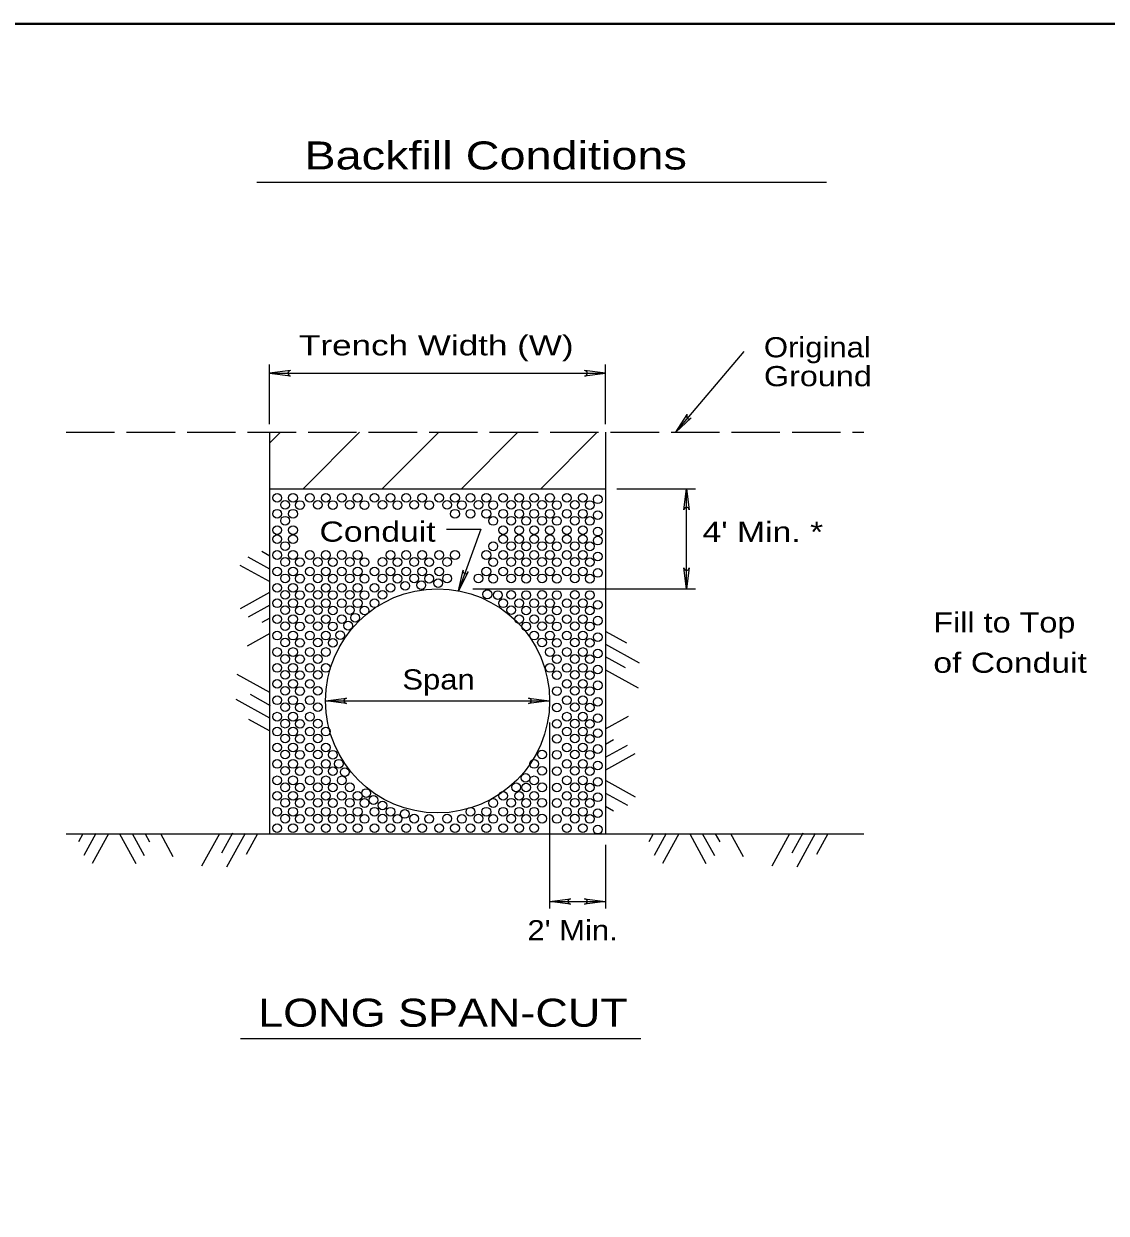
# Model space of a CAD drawing. Extents: x 750.7 to 784.7, y 834.8 to 878.8.
# Drawn here: x 763.05 to 772.71, y 845.67 to 856.28 of the extents above; entities that cross this region are included whole.
import ezdxf

# ---------------------------------------------------------------- set-up
doc = ezdxf.new("R2010")
doc.units = 0
doc.header["$LTSCALE"] = 0.072
doc.linetypes.add('LONG_DASHED', pattern=[7.5, 6, -1.5])
doc.layers.add('1', color=7, linetype='Continuous', lineweight=13)
doc.layers.add('47', color=7, linetype='Continuous', lineweight=13)

msp = doc.modelspace()

# ---------------------------------------------------------------- linework, layer by layer
at = {"layer": '1', "lineweight": 40}
msp.add_line((752.65083, 856.28433), (784.15083, 856.28433), dxfattribs=at)
at = {"layer": '1'}
for p, q in [((765.12592, 854.87), (770.20992, 854.87)), ((768.86525, 852.63842), (769.47633, 853.36033)), ((765.2395, 852.71117), (765.2395, 853.24292)), ((768.2395, 852.71117), (768.2395, 853.24292)), ((765.2395, 853.16492), (768.2395, 853.16492)), ((765.2395, 852.63842), (765.2395, 849.05517)), ((765.2395, 852.54192), (765.336, 852.63842)), ((765.53858, 852.13383), (766.04308, 852.63842)), ((766.24567, 852.13383), (766.75017, 852.63842)), ((766.95275, 852.13383), (767.45725, 852.63842)), ((767.65983, 852.13383), (768.16433, 852.63842)), ((768.2395, 852.63842), (768.2395, 849.05517)), ((765.2395, 852.13383), (768.2395, 852.13383)), ((768.3405, 852.13383), (769.04183, 852.13383)), ((768.96192, 851.24025), (768.96192, 852.13383)), ((765.24342, 851.41692), (765.04792, 851.52475)), ((765.242, 851.5335), (765.17067, 851.57283)), ((765.2395, 851.30483), (764.97692, 851.44975)), ((765.2395, 851.20692), (764.97692, 851.062)), ((767.05342, 851.24025), (769.04183, 851.24025)), ((765.24342, 851.09483), (765.04792, 850.987)), ((765.242, 850.97825), (765.17067, 850.93892)), ((765.2425, 850.84192), (765.03842, 850.72933)), ((768.242, 850.85983), (768.42642, 850.75808)), ((768.23808, 850.74775), (768.53925, 850.58158)), ((768.23417, 850.63575), (768.41258, 850.53733)), ((765.242, 850.31475), (764.951, 850.47533)), ((768.2395, 850.51858), (768.5305, 850.358)), ((765.24342, 850.08558), (764.94225, 850.25175)), ((765.24733, 850.19758), (765.06892, 850.296)), ((765.7395, 850.2405), (767.7395, 850.2405)), ((768.239, 849.99142), (768.44308, 850.104)), ((765.2395, 849.9735), (765.05508, 850.07525)), ((767.7395, 850.04683), (767.7395, 848.38733)), ((768.2395, 849.85508), (768.31083, 849.89442)), ((768.23808, 849.7385), (768.43358, 849.84633)), ((768.242, 849.62642), (768.50458, 849.77133)), ((768.242, 849.5285), (768.50458, 849.38358)), ((768.23808, 849.41642), (768.43358, 849.30858)), ((768.2395, 849.29983), (768.31083, 849.2605)), ((763.42408, 849.05517), (770.54342, 849.05517)), ((763.57342, 849.05517), (763.53408, 848.98383)), ((763.69, 849.05658), (763.58217, 848.86108)), ((763.80208, 849.05267), (763.65717, 848.79008)), ((763.9, 849.05267), (764.04492, 848.79008)), ((764.01208, 849.05658), (764.11992, 848.86108)), ((764.12867, 849.05517), (764.168, 848.98383)), ((764.265, 849.05567), (764.37758, 848.85158)), ((764.79217, 849.05517), (764.63158, 848.76417)), ((764.90933, 849.0605), (764.81092, 848.88208)), ((765.02133, 849.05658), (764.85517, 848.75542)), ((765.13342, 849.05267), (765.03167, 848.86825)), ((768.66358, 849.05517), (768.62425, 848.98383)), ((768.78017, 849.05658), (768.67233, 848.86108)), ((768.89225, 849.05267), (768.74733, 848.79008)), ((768.99017, 849.05267), (769.13508, 848.79008)), ((769.10225, 849.05658), (769.21008, 848.86108)), ((769.21883, 849.05517), (769.25817, 848.98383)), ((769.35517, 849.05567), (769.46775, 848.85158)), ((769.88233, 849.05517), (769.72175, 848.76417)), ((769.9995, 849.0605), (769.90108, 848.88208)), ((770.1115, 849.05658), (769.94533, 848.75542)), ((770.22358, 849.05267), (770.12183, 848.86825)), ((768.2395, 848.95567), (768.2395, 848.38733)), ((767.7395, 848.4495), (768.2395, 848.4495)), ((764.97883, 847.22583), (768.55458, 847.22583))]:
    msp.add_line(p, q, dxfattribs=at)
at = {"layer": '1', "linetype": 'LONG_DASHED'}
msp.add_line((763.42408, 852.63842), (770.54342, 852.63842), dxfattribs=at)
at = {"layer": '1', "lineweight": 40}
msp.add_lwpolyline([(784.15083, 835.28433), (752.65083, 835.28433), (752.65083, 856.28433), (784.15083, 856.28433)], dxfattribs=at)
at = {"layer": '1'}
msp.add_lwpolyline([(766.82042, 851.77392), (767.12475, 851.77392), (766.92558, 851.223)], dxfattribs=at)
for centre, radius in [((765.30705, 852.05311), 0.03892), ((765.37808, 851.99097), 0.03892), ((765.44908, 852.05314), 0.03892), ((765.51124, 851.98864), 0.03892), ((765.59996, 852.05311), 0.03892), ((765.67099, 851.99097), 0.03892), ((765.74199, 852.05314), 0.03892), ((765.80416, 851.98864), 0.03892), ((765.88405, 852.05311), 0.03892), ((765.95508, 851.99097), 0.03892), ((766.02608, 852.05314), 0.03892), ((766.08824, 851.98864), 0.03892), ((766.17696, 852.05311), 0.03892), ((766.24799, 851.99097), 0.03892), ((766.31899, 852.05314), 0.03892), ((766.38116, 851.98864), 0.03892), ((766.46005, 852.05311), 0.03892), ((766.53108, 851.99097), 0.03892), ((766.60208, 852.05314), 0.03892), ((766.66424, 851.98864), 0.03892), ((766.75296, 852.05311), 0.03892), ((766.82399, 851.99097), 0.03892), ((766.89499, 852.05314), 0.03892), ((766.95716, 851.98864), 0.03892), ((767.03263, 852.05311), 0.03892), ((767.10366, 851.99097), 0.03892), ((767.17466, 852.05314), 0.03892), ((767.23683, 851.98864), 0.03892), ((767.32555, 852.05311), 0.03892), ((767.39658, 851.99097), 0.03892), ((767.46758, 852.05314), 0.03892), ((767.52974, 851.98864), 0.03892), ((767.6008, 852.05311), 0.03892), ((767.67183, 851.99097), 0.03892), ((767.74283, 852.05314), 0.03892), ((767.80499, 851.98864), 0.03892), ((767.89371, 852.05311), 0.03892), ((767.96474, 851.99097), 0.03892), ((768.03574, 852.05314), 0.03892), ((768.09791, 851.98864), 0.03892), ((768.16891, 852.03981), 0.03892), ((765.30705, 851.91103), 0.03892), ((765.44908, 851.91106), 0.03892), ((766.89499, 851.91106), 0.03892), ((767.03263, 851.91103), 0.03892), ((767.17466, 851.91106), 0.03892), ((767.32555, 851.91103), 0.03892), ((767.46758, 851.91106), 0.03892), ((767.6008, 851.91103), 0.03892), ((767.74283, 851.91106), 0.03892), ((767.89371, 851.91103), 0.03892), ((768.03574, 851.91106), 0.03892), ((768.16891, 851.89772), 0.03892), ((765.30705, 851.76453), 0.03892), ((765.37808, 851.84889), 0.03892), ((765.44908, 851.76456), 0.03892), ((767.23683, 851.84656), 0.03892), ((767.32555, 851.76453), 0.03892), ((767.39658, 851.84889), 0.03892), ((767.46758, 851.76456), 0.03892), ((767.52974, 851.84656), 0.03892), ((767.6008, 851.76453), 0.03892), ((767.67183, 851.84889), 0.03892), ((767.74283, 851.76456), 0.03892), ((767.80499, 851.84656), 0.03892), ((767.89371, 851.76453), 0.03892), ((767.96474, 851.84889), 0.03892), ((768.03574, 851.76456), 0.03892), ((768.09791, 851.84656), 0.03892), ((765.30705, 851.68461), 0.03892), ((765.44908, 851.68464), 0.03892), ((767.32555, 851.68461), 0.03892), ((767.46758, 851.68464), 0.03892), ((767.6008, 851.68461), 0.03892), ((767.74283, 851.68464), 0.03892), ((767.89371, 851.68461), 0.03892), ((768.03574, 851.68464), 0.03892), ((768.16891, 851.75122), 0.03892), ((768.16891, 851.67131), 0.03892), ((765.37808, 851.62247), 0.03892), ((767.23683, 851.62014), 0.03892), ((767.39658, 851.62247), 0.03892), ((767.52974, 851.62014), 0.03892), ((767.67183, 851.62247), 0.03892), ((767.80499, 851.62014), 0.03892), ((767.96474, 851.62247), 0.03892), ((768.09791, 851.62014), 0.03892), ((765.30705, 851.54253), 0.03892), ((765.37808, 851.48039), 0.03892), ((765.44908, 851.54256), 0.03892), ((765.51124, 851.47806), 0.03892), ((765.59996, 851.54253), 0.03892), ((765.67099, 851.48039), 0.03892), ((765.74199, 851.54256), 0.03892), ((765.80416, 851.47806), 0.03892), ((765.88405, 851.54253), 0.03892), ((765.95508, 851.48039), 0.03892), ((766.02608, 851.54256), 0.03892), ((766.08824, 851.47806), 0.03892), ((766.24799, 851.48039), 0.03892), ((766.31899, 851.54256), 0.03892), ((766.38116, 851.47806), 0.03892), ((766.46005, 851.54253), 0.03892), ((766.53108, 851.48039), 0.03892), ((766.60208, 851.54256), 0.03892), ((766.66424, 851.47806), 0.03892), ((766.75296, 851.54253), 0.03892), ((766.82399, 851.48039), 0.03892), ((766.89499, 851.54256), 0.03892), ((767.17466, 851.54256), 0.03892), ((767.23683, 851.47806), 0.03892), ((767.32555, 851.54253), 0.03892), ((767.39658, 851.48039), 0.03892), ((767.46758, 851.54256), 0.03892), ((767.52974, 851.47806), 0.03892), ((767.6008, 851.54253), 0.03892), ((767.67183, 851.48039), 0.03892), ((767.74283, 851.54256), 0.03892), ((767.80499, 851.47806), 0.03892), ((767.89371, 851.54253), 0.03892), ((767.96474, 851.48039), 0.03892), ((768.03574, 851.54256), 0.03892), ((768.09791, 851.47806), 0.03892), ((768.16891, 851.52922), 0.03892), ((765.30705, 851.39603), 0.03892), ((765.37808, 851.33389), 0.03892), ((765.44908, 851.39606), 0.03892), ((765.59996, 851.39603), 0.03892), ((765.67099, 851.33389), 0.03892), ((765.74199, 851.39606), 0.03892), ((765.88405, 851.39603), 0.03892), ((765.95508, 851.33389), 0.03892), ((766.02608, 851.39606), 0.03892), ((766.17696, 851.39603), 0.03892), ((766.24799, 851.33389), 0.03892), ((766.31899, 851.39606), 0.03892), ((766.46005, 851.39603), 0.03892), ((766.53108, 851.33389), 0.03892), ((766.60208, 851.39606), 0.03892), ((766.75296, 851.39603), 0.03892), ((766.82399, 851.33389), 0.03892), ((767.10366, 851.33389), 0.03892), ((767.17466, 851.39606), 0.03892), ((767.32555, 851.39603), 0.03892), ((767.39658, 851.33389), 0.03892), ((767.46758, 851.39606), 0.03892), ((767.6008, 851.39603), 0.03892), ((767.67183, 851.33389), 0.03892), ((767.74283, 851.39606), 0.03892), ((767.89371, 851.39603), 0.03892), ((767.96474, 851.33389), 0.03892), ((768.03574, 851.39606), 0.03892), ((768.16891, 851.38272), 0.03892), ((765.30705, 851.24944), 0.03892), ((765.44908, 851.24947), 0.03892), ((765.51124, 851.33156), 0.03892), ((765.59996, 851.24944), 0.03892), ((765.74199, 851.24947), 0.03892), ((765.80416, 851.33156), 0.03892), ((765.88405, 851.24944), 0.03892), ((766.02608, 851.24947), 0.03892), ((766.08824, 851.33156), 0.03892), ((766.17696, 851.24944), 0.03892), ((766.31899, 851.24947), 0.03892), ((766.38116, 851.33156), 0.03892), ((766.45115, 851.26725), 0.03892), ((766.59425, 851.27379), 0.03892), ((766.66424, 851.33156), 0.03892), ((766.74508, 851.29154), 0.03892), ((767.23683, 851.33156), 0.03892), ((767.52974, 851.33156), 0.03892), ((767.80499, 851.33156), 0.03892), ((768.09791, 851.33156), 0.03892), ((765.37808, 851.18731), 0.03892), ((765.51124, 851.18497), 0.03892), ((765.67099, 851.18731), 0.03892), ((766.7395, 850.2405), 1), ((765.80416, 851.18497), 0.03892), ((765.95508, 851.18731), 0.03892), ((766.08824, 851.18497), 0.03892), ((766.24799, 851.18731), 0.03892), ((767.18356, 851.1917), 0.03892), ((767.27675, 851.18495), 0.03892), ((767.39658, 851.18731), 0.03892), ((767.52974, 851.18497), 0.03892), ((767.67183, 851.18731), 0.03892), ((767.80499, 851.18497), 0.03892), ((767.96474, 851.18731), 0.03892), ((768.09791, 851.18497), 0.03892), ((765.30705, 851.11178), 0.03892), ((765.37808, 851.04964), 0.03892), ((765.44908, 851.11181), 0.03892), ((765.51124, 851.04731), 0.03892), ((765.59996, 851.11178), 0.03892), ((765.67099, 851.04964), 0.03892), ((765.74199, 851.11181), 0.03892), ((765.80416, 851.04731), 0.03892), ((765.88405, 851.11178), 0.03892), ((765.95508, 851.04964), 0.03892), ((766.02608, 851.11181), 0.03892), ((766.08824, 851.04731), 0.03892), ((766.17696, 851.11178), 0.03892), ((767.32555, 851.11178), 0.03892), ((767.39658, 851.04964), 0.03892), ((767.46758, 851.11181), 0.03892), ((767.52974, 851.04731), 0.03892), ((767.6008, 851.11178), 0.03892), ((767.67183, 851.04964), 0.03892), ((767.74283, 851.11181), 0.03892), ((767.80499, 851.04731), 0.03892), ((767.89371, 851.11178), 0.03892), ((767.96474, 851.04964), 0.03892), ((768.03574, 851.11181), 0.03892), ((768.09791, 851.04731), 0.03892), ((768.16891, 851.09847), 0.03892), ((765.30705, 850.96969), 0.03892), ((765.44908, 850.96972), 0.03892), ((765.59996, 850.96969), 0.03892), ((765.74199, 850.96972), 0.03892), ((765.88405, 850.96969), 0.03892), ((765.94175, 850.91202), 0.03892), ((766.00384, 850.98305), 0.03892), ((767.46758, 850.96972), 0.03892), ((767.6008, 850.96969), 0.03892), ((767.74283, 850.96972), 0.03892), ((767.89371, 850.96969), 0.03892), ((768.03574, 850.96972), 0.03892), ((768.16891, 850.95639), 0.03892), ((765.30705, 850.82319), 0.03892), ((765.37808, 850.90756), 0.03892), ((765.44908, 850.82322), 0.03892), ((765.51124, 850.90522), 0.03892), ((765.59996, 850.82319), 0.03892), ((765.67099, 850.90756), 0.03892), ((765.74199, 850.82322), 0.03892), ((765.80416, 850.90522), 0.03892), ((765.87075, 850.82761), 0.03892), ((767.52974, 850.90522), 0.03892), ((767.6008, 850.82319), 0.03892), ((767.67183, 850.90756), 0.03892), ((767.74283, 850.82322), 0.03892), ((767.80499, 850.90522), 0.03892), ((767.89371, 850.82319), 0.03892), ((767.96474, 850.90756), 0.03892), ((768.03574, 850.82322), 0.03892), ((768.09791, 850.90522), 0.03892), ((768.16891, 850.80989), 0.03892), ((765.37808, 850.76106), 0.03892), ((765.51124, 850.75872), 0.03892), ((765.67099, 850.76106), 0.03892), ((765.80416, 850.75872), 0.03892), ((767.67183, 850.76106), 0.03892), ((767.80499, 850.75872), 0.03892), ((767.96474, 850.76106), 0.03892), ((768.09791, 850.75872), 0.03892), ((765.30705, 850.67661), 0.03892), ((765.37808, 850.61447), 0.03892), ((765.44908, 850.67664), 0.03892), ((765.51124, 850.61214), 0.03892), ((765.59996, 850.67661), 0.03892), ((765.67099, 850.61447), 0.03892), ((765.74199, 850.67664), 0.03892), ((767.74283, 850.67664), 0.03892), ((767.80499, 850.61214), 0.03892), ((767.89371, 850.67661), 0.03892), ((767.96474, 850.61447), 0.03892), ((768.03574, 850.67664), 0.03892), ((768.09791, 850.61214), 0.03892), ((768.16891, 850.66331), 0.03892), ((765.30705, 850.53461), 0.03892), ((765.44908, 850.53464), 0.03892), ((765.59996, 850.53461), 0.03892), ((765.74199, 850.53464), 0.03892), ((767.74283, 850.53464), 0.03892), ((767.89371, 850.53461), 0.03892), ((768.03574, 850.53464), 0.03892), ((768.16891, 850.52131), 0.03892), ((765.30705, 850.39253), 0.03892), ((765.37808, 850.47247), 0.03892), ((765.44908, 850.39256), 0.03892), ((765.51124, 850.47014), 0.03892), ((765.59996, 850.39253), 0.03892), ((765.67099, 850.47247), 0.03892), ((767.80499, 850.47014), 0.03892), ((767.89371, 850.39253), 0.03892), ((767.96474, 850.47247), 0.03892), ((768.03574, 850.39256), 0.03892), ((768.09791, 850.47014), 0.03892), ((768.16891, 850.37922), 0.03892), ((765.37808, 850.33039), 0.03892), ((765.51124, 850.32806), 0.03892), ((765.67099, 850.33039), 0.03892), ((767.80499, 850.32806), 0.03892), ((767.96474, 850.33039), 0.03892), ((768.09791, 850.32806), 0.03892), ((765.30705, 850.24603), 0.03892), ((765.37808, 850.18389), 0.03892), ((765.44908, 850.24606), 0.03892), ((765.51124, 850.18156), 0.03892), ((765.59996, 850.24603), 0.03892), ((765.67099, 850.18389), 0.03892), ((767.80499, 850.18156), 0.03892), ((767.89371, 850.24603), 0.03892), ((767.96474, 850.18389), 0.03892), ((768.03574, 850.24606), 0.03892), ((768.09791, 850.18156), 0.03892), ((768.16891, 850.23272), 0.03892), ((765.30705, 850.09944), 0.03892), ((765.44908, 850.09947), 0.03892), ((765.59996, 850.09944), 0.03892), ((767.89371, 850.09944), 0.03892), ((768.03574, 850.09947), 0.03892), ((768.16891, 850.08614), 0.03892), ((765.30705, 849.96628), 0.03892), ((765.37808, 850.03731), 0.03892), ((765.44908, 849.96631), 0.03892), ((765.51124, 850.03497), 0.03892), ((765.59996, 849.96628), 0.03892), ((765.67099, 850.03731), 0.03892), ((765.74199, 849.96631), 0.03892), ((767.80499, 850.03497), 0.03892), ((767.89371, 849.96628), 0.03892), ((767.96474, 850.03731), 0.03892), ((768.03574, 849.96631), 0.03892), ((768.09791, 850.03497), 0.03892), ((768.16891, 849.95297), 0.03892), ((765.37808, 849.90414), 0.03892), ((765.51124, 849.90181), 0.03892), ((765.67099, 849.90414), 0.03892), ((767.80499, 849.90181), 0.03892), ((767.96474, 849.90414), 0.03892), ((768.09791, 849.90181), 0.03892), ((765.30705, 849.82419), 0.03892), ((765.37808, 849.76206), 0.03892), ((765.44908, 849.82422), 0.03892), ((765.51124, 849.75972), 0.03892), ((765.59996, 849.82419), 0.03892), ((765.67099, 849.76206), 0.03892), ((765.74199, 849.82422), 0.03892), ((765.80416, 849.75972), 0.03892), ((767.67183, 849.76206), 0.03892), ((767.80499, 849.75972), 0.03892), ((767.89371, 849.82419), 0.03892), ((767.96474, 849.76206), 0.03892), ((768.03574, 849.82422), 0.03892), ((768.09791, 849.75972), 0.03892), ((768.16891, 849.81089), 0.03892), ((765.30705, 849.67769), 0.03892), ((765.44908, 849.67772), 0.03892), ((765.59996, 849.67769), 0.03892), ((765.74199, 849.67772), 0.03892), ((765.85742, 849.67979), 0.03892), ((767.6008, 849.67769), 0.03892), ((767.89371, 849.67769), 0.03892), ((768.03574, 849.67772), 0.03892), ((768.16891, 849.66439), 0.03892), ((765.30705, 849.53111), 0.03892), ((765.37808, 849.61556), 0.03892), ((765.44908, 849.53114), 0.03892), ((765.51124, 849.61322), 0.03892), ((765.59996, 849.53111), 0.03892), ((765.67099, 849.61556), 0.03892), ((765.74199, 849.53114), 0.03892), ((765.80416, 849.61322), 0.03892), ((765.88405, 849.53111), 0.03892), ((765.91067, 849.60429), 0.03892), ((767.52526, 849.55334), 0.03892), ((767.6008, 849.53111), 0.03892), ((767.67183, 849.61556), 0.03892), ((767.80499, 849.61322), 0.03892), ((767.89371, 849.53111), 0.03892), ((767.96474, 849.61556), 0.03892), ((768.03574, 849.53114), 0.03892), ((768.09791, 849.61322), 0.03892), ((765.37808, 849.46897), 0.03892), ((765.51124, 849.46664), 0.03892), ((765.67099, 849.46897), 0.03892), ((765.80416, 849.46664), 0.03892), ((765.95508, 849.46897), 0.03892), ((767.44093, 849.46892), 0.03892), ((767.52974, 849.46664), 0.03892), ((767.67183, 849.46897), 0.03892), ((767.80499, 849.46664), 0.03892), ((767.96474, 849.46897), 0.03892), ((768.09791, 849.46664), 0.03892), ((768.16891, 849.51781), 0.03892), ((765.30705, 849.39344), 0.03892), ((765.37808, 849.33131), 0.03892), ((765.44908, 849.39347), 0.03892), ((765.51124, 849.32897), 0.03892), ((765.59996, 849.39344), 0.03892), ((765.67099, 849.33131), 0.03892), ((765.74199, 849.39347), 0.03892), ((765.80416, 849.32897), 0.03892), ((765.88405, 849.39344), 0.03892), ((765.95508, 849.33131), 0.03892), ((766.02608, 849.39347), 0.03892), ((766.08824, 849.32897), 0.03892), ((766.1015, 849.41787), 0.03892), ((766.16808, 849.35571), 0.03892), ((767.23683, 849.32897), 0.03892), ((767.32555, 849.39344), 0.03892), ((767.39658, 849.33131), 0.03892), ((767.46758, 849.39347), 0.03892), ((767.52974, 849.32897), 0.03892), ((767.6008, 849.39344), 0.03892), ((767.67183, 849.33131), 0.03892), ((767.80499, 849.32897), 0.03892), ((767.89371, 849.39344), 0.03892), ((767.96474, 849.33131), 0.03892), ((768.03574, 849.39347), 0.03892), ((768.09791, 849.32897), 0.03892), ((768.16891, 849.38014), 0.03892), ((765.30705, 849.25136), 0.03892), ((765.44908, 849.25139), 0.03892), ((765.59996, 849.25136), 0.03892), ((765.74199, 849.25139), 0.03892), ((765.88405, 849.25136), 0.03892), ((766.02608, 849.25139), 0.03892), ((766.17696, 849.25136), 0.03892), ((766.248, 849.30679), 0.03892), ((766.31899, 849.25139), 0.03892), ((766.44775, 849.23137), 0.03892), ((767.03263, 849.25136), 0.03892), ((767.17466, 849.25139), 0.03892), ((767.32555, 849.25136), 0.03892), ((767.46758, 849.25139), 0.03892), ((767.6008, 849.25136), 0.03892), ((767.89371, 849.25136), 0.03892), ((768.03574, 849.25139), 0.03892), ((768.16891, 849.23806), 0.03892), ((765.30705, 849.10486), 0.03892), ((765.37808, 849.18922), 0.03892), ((765.44908, 849.10489), 0.03892), ((765.51124, 849.18689), 0.03892), ((765.59996, 849.10486), 0.03892), ((765.67099, 849.18922), 0.03892), ((765.74199, 849.10489), 0.03892), ((765.80416, 849.18689), 0.03892), ((765.88405, 849.10486), 0.03892), ((765.95508, 849.18922), 0.03892), ((766.02608, 849.10489), 0.03892), ((766.08824, 849.18689), 0.03892), ((766.17696, 849.10486), 0.03892), ((766.24799, 849.18922), 0.03892), ((766.31899, 849.10489), 0.03892), ((766.38116, 849.18689), 0.03892), ((766.46005, 849.10486), 0.03892), ((766.53108, 849.18922), 0.03892), ((766.60208, 849.10489), 0.03892), ((766.66424, 849.18689), 0.03892), ((766.75296, 849.10486), 0.03892), ((766.82399, 849.18922), 0.03892), ((766.89499, 849.10489), 0.03892), ((766.95716, 849.18689), 0.03892), ((767.03263, 849.10486), 0.03892), ((767.10366, 849.18922), 0.03892), ((767.17466, 849.10489), 0.03892), ((767.23683, 849.18689), 0.03892), ((767.32555, 849.10486), 0.03892), ((767.39658, 849.18922), 0.03892), ((767.46758, 849.10489), 0.03892), ((767.52974, 849.18689), 0.03892), ((767.6008, 849.10486), 0.03892), ((767.67183, 849.18922), 0.03892), ((767.80499, 849.18689), 0.03892), ((767.89371, 849.10486), 0.03892), ((767.96474, 849.18922), 0.03892), ((768.03574, 849.10489), 0.03892), ((768.09791, 849.18689), 0.03892), ((768.16891, 849.09156), 0.03892)]:
    msp.add_circle(centre, radius, dxfattribs=at)
at = {"layer": '47'}
for points in [[(765.427, 853.18833), (765.2395, 853.16492), (765.427, 853.1415)], [(768.052, 853.1415), (768.2395, 853.16492), (768.052, 853.18833)], [(769.00425, 852.76642), (768.86525, 852.63842), (768.9685, 852.79667)], [(768.9385, 851.94633), (768.96192, 852.13383), (768.98533, 851.94633)], [(767.01133, 851.39133), (766.92558, 851.223), (766.96733, 851.40733)], [(768.98533, 851.42775), (768.96192, 851.24025), (768.9385, 851.42775)], [(765.927, 850.21708), (765.7395, 850.2405), (765.927, 850.26392)], [(767.552, 850.26392), (767.7395, 850.2405), (767.552, 850.21708)], [(767.927, 848.42608), (767.7395, 848.4495), (767.927, 848.47292)], [(768.052, 848.47292), (768.2395, 848.4495), (768.052, 848.42608)]]:
    msp.add_lwpolyline(points, dxfattribs=at)
for centre, start, end in [((765.42701, 853.16493), 90, 270), ((768.05199, 853.16494), 270, 90), ((768.98639, 852.78154), 139.75297, 319.75297), ((768.96192, 851.94633), 0, 180), ((766.98932, 851.39934), 160.12536, 340.12536), ((768.96191, 851.42776), 180, 0), ((765.92701, 850.24051), 90, 270), ((767.55199, 850.24049), 270, 90), ((767.92701, 848.44951), 90, 270), ((768.05199, 848.44949), 270, 90)]:
    msp.add_arc(centre, 0.02342, start, end, dxfattribs=at)

# ---------------------------------------------------------------- texts
at = {"layer": '1'}
for s, height, width, p in [('Backfill Conditions', 0.25, 1.25, (765.55083, 854.98392)), ('Trench Width (W)', 0.18, 1.3, (765.5025, 853.32425)), ('Original', 0.18, 1.15, (769.65258, 853.30725)), ('Ground', 0.18, 1.2, (769.65258, 853.04925)), ('Conduit', 0.18, 1.25, (765.68558, 851.6615)), ("4' Min. *", 0.18, 1.25, (769.104, 851.65883)), ('Fill to Top', 0.18, 1.2, (771.16475, 850.85108)), ('of Conduit', 0.18, 1.25, (771.16475, 850.49108)), ('Span', 0.18, 1.15, (766.425, 850.34208)), ("2' Min.", 0.18, 1.15, (767.54158, 848.10317)), ('LONG SPAN-CUT', 0.25, 1.2, (765.13825, 847.33217))]:
    msp.add_text(s, height=height, dxfattribs=dict(at, width=width)).set_placement(p)

doc.saveas('drawing.dxf')
